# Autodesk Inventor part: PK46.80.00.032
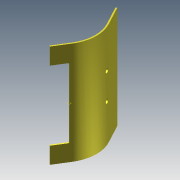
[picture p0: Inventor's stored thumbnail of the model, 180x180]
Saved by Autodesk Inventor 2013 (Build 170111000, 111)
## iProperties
Shininess: 64.0
Length Units: 11269
Angle Units: 11279
Time Units: 11290
Mass Units: 11283
Length Display Precision: 3
Angle Display Precision: 2
Compacted: True
Part Number: PK46.80.00.032
Document SubType Name: Sheet Metal
Created: 2005-01
Material: Steel, Mild
Designer: SAlex
Manufacturer: Standard
Standards Organization: Custom
Density: 7.86 g/cm^3
Flat Pattern Width: 136.565 cm
Flat Pattern Length: 151.087 cm
Flat Pattern Area: 20633.1 cm^2
Sheet Metal Rule: Default
Mass: 119662 g
Surface Area: 19816.5 cm^2
Volume: 15224.2 cm^3
Density: 0.0
Volumn: 0.0
Area: 0.0
PropertySet Name: Model Information
Control State: 0
Master: False
Checked Out: False
Checked Out Date: 2008-10-15
Last Check In Date: 2008-10-15
Author: SAlex
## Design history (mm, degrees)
node "Contour Flange1"
  sketch "Sketch1"
    geometry: L1 (0, 0)-(105.376, 169.988); L2 (118.157, 577.787)-(0, 798.103); A1 r 408 centre (-241.398, 384.956) between (105.376, 169.988) and (118.157, 577.787)
    constraints: 4 end point, 2 point on circle, 2 tangent, 1 centre point, 1 other
    dimensions: "d1" = 60 deg dimension on A1.centre L2.start L1.end; "d2" = 200 distance of L1.start L1.end; "d3" = 408 radius of A1; "d4" = 250 distance of L2.start L2.end; "d5" = 0 horizontal distance of L2.end L1.start
sketch "Sketch2"
  geometry: L1 (1240, -200)-(1240, 0) reference; L2 (0, -200)-(0, 0) reference; L3 (0, -200)-(1240, -200) reference; L4 (200, -200)-(1040, -200); L5 (1040, -200)-(1040, -30); L6 (1040, -30)-(200, -30); L7 (200, -30)-(200, -200)
  constraints: 8 end point, 2 parallel, 1 horizontal, 1 perpendicular, 1 point on line
  dimensions: "d13" = 200 distance between parallel lines of L7 L2; "d14" = 200 distance between parallel lines of L1 L5 (= d13); "d15" = 170 distance between parallel lines of L3 L6
extrude "Extrusion1" cut sketch "Sketch2" stored distance "d16" = 10; taper "d17" = 0 deg
fillet "Fillet1" dims "d18" = 10
workplane "Work Plane1"
sketch "Sketch4"
  geometry: L1 (0, 250)-(0, 0) reference; L2 (1240, 250)-(0, 250) reference; C1 r 25 at (460, -45); C2 r 25 at (780, -45)
  constraints: 2 centre point, 1 equal radius
  dimensions: "d24" = 0 vertical distance of C2.centre C1.centre; "d25" = 295 distance from line of C1.centre L2; "d26" = 50 diameter of C1; "d27" = 320 distance of C2.centre C1.centre; "d28" = 460 distance from line of C1.centre L1
extrude "Extrusion3" cut sketch "Sketch4" stored distance "d29" = 10; taper "d30" = 0 deg
body "Solid1"
face "Plate1" dims "d6" = 1240, "d7" = 16 (= BendReliefWidth), "d9" = 32 (= MinimumRemnant), "d11" = 16 (= BendRadius), "d12" = 0.5, "Thickness" = 16
bend "Bend1" dims "d7" = 16 (= BendReliefWidth), "d8" = 8 (= BendReliefDepth), "d9" = 32 (= MinimumRemnant), "d10" = 16 (= BendRadius), "d11" = 16 (= BendRadius), "d12" = 0.5, "SeamGap" = 0.01, "Thickness" = 16
node "FlatPattern"
feature "FlatPatternExtrusion2" dims "d0" = 16 (derived)
other parameters: "BendRadius" = 16 (= Thickness), "BendReliefWidth" = 16 (= Thickness), "BendReliefDepth" = 8 (= 0.5 x Thickness), "CornerReliefSize" = 64 (= 4 x Thickness), "MinimumRemnant" = 32 (= 2 x Thickness), "TransitionRadius" = 16 (= BendRadius), "JacobiRadiusSize" = 16 (= Thickness), "GapSize" = 16 (= Thickness)
